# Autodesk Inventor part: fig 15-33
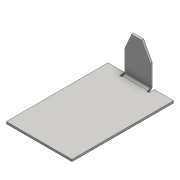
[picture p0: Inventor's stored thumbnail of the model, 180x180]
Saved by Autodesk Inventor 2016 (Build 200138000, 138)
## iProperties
Created: 2015-07
Part Number: fig 15-33
Material: Generic
Document SubType Name: Sheet Metal
Designer: Sandeep
Density: 1 g/cm^3
Sheet Metal Rule: Default_mm
Appearance: Default
Author: Sandeep
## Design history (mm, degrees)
node "Face1"
  sketch "Sketch1"
    geometry: L1 (-7.97, 10.943)-(7.467, 10.943); L2 (7.467, 10.943)-(7.467, -12.976); L3 (7.467, -12.976)-(-7.97, -12.976); L4 (-7.97, -12.976)-(-7.97, 10.943); 1 further point
    constraints: 8 end point, 2 parallel, 1 horizontal, 1 perpendicular
node "Face3"
  sketch "Sketch3"
    geometry: L1 (0, -0.5)-(15.436, -0.5) reference; L2 (10.402, -0.5)-(10.402, -5.794); L3 (10.402, -5.794)-(8.357, -9.576); L4 (8.357, -9.576)-(6.065, -9.576); L5 (6.065, -9.576)-(4.475, -6.057); L6 (4.475, -6.057)-(4.475, -0.5); L7 (10.402, -0.5)-(4.475, -0.5); 1 further point
    constraints: 12 end point, 2 perpendicular, 2 point on line, 1 collinear, 1 vertical
body "Solid1"
face "Plate1" dims "Thickness" = 0.5
face "Plate3" dims "d6" = 0.5 (= BendRadius), "d7" = 0.5 (= BendReliefWidth), "d9" = 1 (= MinimumRemnant), "Thickness" = 0.5
bend "Bend2" dims "d6" = 0.5 (= BendRadius), "d7" = 0.5 (= BendReliefWidth), "d8" = 0.25 (= BendReliefDepth), "d9" = 1 (= MinimumRemnant), "d10" = 0.5 (= BendRadius), "SeamGap" = 0.01, "Thickness" = 0.5
other parameters: "BendRadius" = 0.5 (= Thickness), "BendReliefWidth" = 0.5 (= Thickness), "BendReliefDepth" = 0.25 (= 0.5 x Thickness), "CornerReliefSize" = 2 (= 4 x Thickness), "MinimumRemnant" = 1 (= 2 x Thickness), "TransitionRadius" = 0.5 (= BendRadius), "JacobiRadiusSize" = 0.5 (= BendRadius), "GapSize" = 0.5 (= Thickness), "d0" = 0.5 (= BendRadius)
